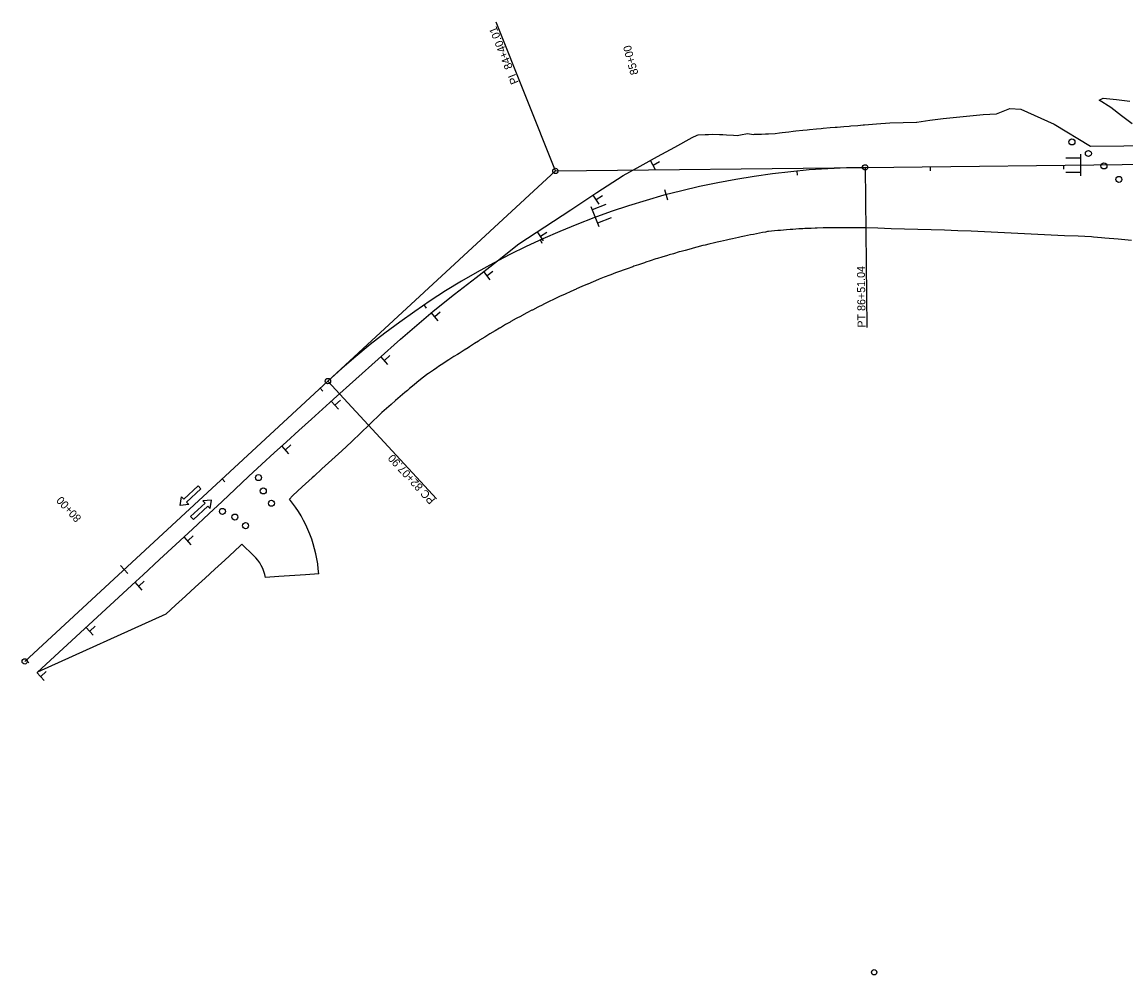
# Model space of a CAD drawing. Extents: x 1710760 to 1712674, y 548603 to 551129.
# Drawn here: x 1710760 to 1711587, y 548603 to 549317 of the extents above; entities that cross this region are included whole.
import ezdxf

# ---------------------------------------------------------------- set-up
doc = ezdxf.new("R2010")
doc.units = 0
for name, color, linetype in [('R_Horz Alg', 7, 'Continuous'), ('R_Horz Alg Annot', 7, 'Continuous'), ('R_MOT', 7, 'Continuous')]:
    doc.layers.add(name, color=color, linetype=linetype)

msp = doc.modelspace()

# ---------------------------------------------------------------- linework, layer by layer
at = {"layer": 'R_Horz Alg'}
for p, q in [((1711391.77, 549208.53), (1711733, 549212.35)), ((1711391.77, 549208.53), (1711733, 549212.35)), ((1710761.95, 548838.38), (1710989.21, 549048.39)), ((1710761.95, 548838.38), (1710989.21, 549048.39))]:
    msp.add_line(p, q, dxfattribs=at)
msp.add_arc((1711398.54, 548605.45), 603.11, 90.64281, 132.74131, dxfattribs=at)
msp.add_arc((1711398.54, 548605.45), 603.11, 90.64281, 132.74131, dxfattribs=at)
at = {"layer": 'R_Horz Alg Annot'}
for p, q in [((1710989.21, 549048.39), (1711159.68, 549205.92)), ((1710989.21, 549048.39), (1711159.68, 549205.92)), ((1711159.68, 549205.92), (1711391.77, 549208.53)), ((1711159.68, 549205.92), (1711391.77, 549208.53))]:
    msp.add_line(p, q, dxfattribs=at)
for points in [[(1711159.68, 549205.92), (1711115.32, 549317.42)], [(1711440.76, 549206.08), (1711440.73, 549209.07)], [(1711540.75, 549207.2), (1711540.72, 549210.2)], [(1711341.11, 549202.81), (1711340.82, 549205.8)], [(1711391.77, 549208.53), (1711393.12, 549088.53)], [(1711241.49, 549191.9), (1711243.56, 549184.17)], [(1711149.75, 549151.57), (1711148.51, 549154.3)], [(1711063.03, 549103.01), (1711061.35, 549105.5)], [(1710989.21, 549048.39), (1711070.66, 548960.26)], [(1710985.45, 549040.83), (1710983.41, 549043.03)], [(1710912, 548972.96), (1710909.97, 548975.16)], [(1710833.81, 548910.23), (1710839.24, 548904.35)], [(1710765.12, 548837.22), (1710763.08, 548839.42)]]:
    msp.add_lwpolyline(points, dxfattribs=at)
for centre in [(1711391.77, 549208.53), (1711391.77, 549208.53), (1711159.68, 549205.92), (1711159.68, 549205.92), (1710989.21, 549048.39), (1710989.21, 549048.39), (1710761.95, 548838.38), (1710761.95, 548838.38), (1711398.54, 548605.45), (1711398.54, 548605.45)]:
    msp.add_circle(centre, 2, dxfattribs=at)
at = {"layer": 'R_MOT'}
for p, q in [((1711490.29, 549248.71), (1711500.24, 549252.66)), ((1711553.08, 549218.34), (1711553.08, 549202.34)), ((1711234.71, 549206.71), (1711230.88, 549213.73)), ((1711232.91, 549210.26), (1711237.7, 549212.87)), ((1711542.16, 549215.7), (1711553.08, 549215.7)), ((1711542.16, 549204.84), (1711553.08, 549204.84)), ((1711192.4, 549181.1), (1711188.02, 549187.79)), ((1711190.32, 549184.49), (1711194.89, 549187.48)), ((1711186.23, 549179.17), (1711192.14, 549164.31)), ((1711197.35, 549180.76), (1711187.2, 549176.72)), ((1711201.36, 549170.67), (1711191.21, 549166.63)), ((1711150.63, 549153.61), (1711146.26, 549160.31)), ((1711148.55, 549157.01), (1711153.12, 549160)), ((1711110.84, 549124.25), (1711105.93, 549130.57)), ((1711108.49, 549127.47), (1711112.8, 549130.81)), ((1711071.7, 549093.63), (1711066.5, 549099.71)), ((1711069.2, 549096.73), (1711073.35, 549100.28)), ((1711034.18, 549060.79), (1711028.85, 549066.76)), ((1711031.61, 549063.84), (1711035.68, 549067.48)), ((1710997.01, 549027.36), (1710991.68, 549033.32)), ((1710994.44, 549030.4), (1710998.51, 549034.04)), ((1710959.9, 548993.87), (1710954.55, 548999.82)), ((1710957.33, 548996.91), (1710961.39, 549000.56)), ((1710886.74, 548925.82), (1710881.32, 548931.71)), ((1710884.13, 548928.83), (1710888.15, 548932.53)), ((1710933.39, 548917.62), (1710924.76, 548926.17)), ((1710972.33, 548903.23), (1710952.37, 548901.91)), ((1710982.3, 548903.89), (1710972.33, 548903.23)), ((1710850.04, 548891.85), (1710844.63, 548897.75)), ((1710847.43, 548894.87), (1710851.46, 548898.56)), ((1710952.37, 548901.91), (1710942.35, 548901.24)), ((1710813.27, 548857.97), (1710807.87, 548863.87)), ((1710810.67, 548860.98), (1710814.7, 548864.67)), ((1710776.51, 548824.09), (1710771.1, 548829.99)), ((1710773.91, 548827.1), (1710777.93, 548830.79))]:
    msp.add_line(p, q, dxfattribs=at)
for points in [[(1711591.96, 549241.26), (1711583.97, 549247.29), (1711575.98, 549253.32), (1711567.17, 549258.94), (1711567.8, 549259.07), (1711570.16, 549260.38), (1711580.17, 549259.31), (1711590.19, 549258.2)], [(1711500.24, 549252.66), (1711508.52, 549252.06), (1711533.48, 549240.83), (1711560.71, 549224.42), (1711610.62, 549224.98)], [(1711308.24, 549233.31), (1711308.88, 549233.33), (1711314.08, 549233.52), (1711317.05, 549233.6), (1711319.27, 549233.64), (1711324.45, 549233.9), (1711327.53, 549234.32), (1711329.57, 549234.59), (1711334.7, 549235.24), (1711337.95, 549235.63), (1711339.83, 549235.85), (1711344.97, 549236.42), (1711348.39, 549236.77), (1711350.12, 549236.94), (1711355.27, 549237.43), (1711358.85, 549237.74), (1711360.42, 549237.88), (1711365.57, 549238.34), (1711369.32, 549238.68), (1711370.73, 549238.8), (1711375.9, 549239.2), (1711379.81, 549239.48), (1711381.07, 549239.57), (1711386.24, 549240.01), (1711390.32, 549240.41), (1711391.41, 549240.51), (1711400.36, 549241.23), (1711410.36, 549242.05), (1711420.36, 549242.08), (1711430.35, 549242.53), (1711430.43, 549242.54), (1711440.34, 549243.88), (1711450.32, 549245.11), (1711460.31, 549246.2), (1711470.3, 549247.21), (1711480.29, 549248.18), (1711490.29, 549248.71)], [(1711265.88, 549232.81), (1711266.66, 549232.92), (1711271.96, 549233.16), (1711274.32, 549233.28), (1711277.23, 549233.43), (1711282.58, 549233.19), (1711285.14, 549233.07), (1711287.92, 549232.92), (1711293.25, 549232.57), (1711295.97, 549232.37), (1711298.46, 549232.87), (1711303.55, 549233.92), (1711308.24, 549233.31)], [(1710845.2, 548898.2), (1710850.63, 548903.21), (1710862.95, 548914.62), (1710875.27, 548926.03), (1710887.59, 548937.44), (1710899.91, 548948.84), (1710909.81, 548958.17), (1710919.71, 548967.5), (1710929.61, 548976.83), (1710939.52, 548986.16), (1710948.84, 548994.59), (1710958.16, 549003.01), (1710967.48, 549011.44), (1710976.8, 549019.87), (1710993.47, 549034.87), (1711010.15, 549049.87), (1711026.82, 549064.87), (1711043.5, 549079.87), (1711055.73, 549090.4), (1711067.97, 549100.92), (1711084.06, 549113.47), (1711100.15, 549126.03), (1711116.24, 549138.58), (1711132.33, 549151.14), (1711151.83, 549163.97), (1711171.33, 549176.8), (1711190.83, 549189.63), (1711210.33, 549202.46), (1711223.3, 549209.57), (1711236.27, 549216.69), (1711249.24, 549223.8), (1711262.22, 549230.91), (1711265.88, 549232.81)], [(1711319.28, 549160.49), (1711318.73, 549160.39), (1711317.21, 549160.12), (1711314.77, 549159.67), (1711310.28, 549158.81), (1711308.08, 549158.37), (1711305.79, 549157.91), (1711301.31, 549156.98), (1711298.98, 549156.49), (1711296.83, 549156.05), (1711292.36, 549155.1), (1711289.89, 549154.56), (1711287.9, 549154.12), (1711283.44, 549153.11), (1711280.84, 549152.5), (1711278.99, 549152.05), (1711274.55, 549150.99), (1711271.83, 549150.32), (1711270.12, 549149.89), (1711265.69, 549148.76), (1711262.84, 549148.01), (1711261.28, 549147.59), (1711256.87, 549146.39), (1711253.9, 549145.55), (1711252.48, 549145.15), (1711248.09, 549143.88), (1711245, 549142.96), (1711243.72, 549142.57), (1711239.36, 549141.23), (1711236.14, 549140.25), (1711234.99, 549139.9), (1711230.64, 549138.53), (1711227.31, 549137.43), (1711226.31, 549137.1), (1711221.99, 549135.63), (1711218.54, 549134.43), (1711217.68, 549134.13), (1711213.37, 549132.64), (1711209.8, 549131.36), (1711209.07, 549131.1), (1711204.8, 549129.5), (1711201.13, 549128.09), (1711200.55, 549127.86), (1711196.3, 549126.19), (1711192.53, 549124.67), (1711192.07, 549124.48), (1711187.86, 549122.74), (1711183.97, 549121.13), (1711183.65, 549121), (1711179.44, 549119.23), (1711175.45, 549117.49), (1711175.27, 549117.4), (1711171.11, 549115.52), (1711167.03, 549113.64), (1711166.97, 549113.61), (1711162.83, 549111.71), (1711158.7, 549109.77), (1711158.63, 549109.74), (1711154.6, 549107.79), (1711150.51, 549105.76), (1711150.32, 549105.67), (1711146.44, 549103.72), (1711142.37, 549101.66), (1711142.05, 549101.49), (1711138.33, 549099.54), (1711134.32, 549097.38), (1711133.88, 549097.14), (1711130.32, 549095.19), (1711126.33, 549092.99), (1711125.77, 549092.68), (1711122.36, 549090.74), (1711118.42, 549088.44), (1711117.75, 549088.05), (1711114.5, 549086.12), (1711110.59, 549083.78), (1711109.8, 549083.31), (1711106.71, 549081.4), (1711102.85, 549078.97), (1711101.95, 549078.4), (1711099.01, 549076.52), (1711095.18, 549074.05), (1711094.17, 549073.39), (1711091.37, 549071.54), (1711087.48, 549069.16), (1711086.33, 549068.46), (1711083.59, 549066.77), (1711079.73, 549064.34), (1711078.47, 549063.54), (1711075.97, 549061.76), (1711072.16, 549059.23), (1711070.8, 549058.34), (1711068.36, 549056.71), (1711064.57, 549054.15), (1711063.42, 549053.36), (1711063.11, 549053.15), (1711060.91, 549051.42), (1711057.35, 549048.56), (1711055.86, 549047.36), (1711053.81, 549045.67), (1711050.3, 549042.75), (1711048.72, 549041.45), (1711046.76, 549039.87), (1711043.3, 549036.89), (1711041.65, 549035.45), (1711039.87, 549033.88), (1711036.46, 549030.85), (1711034.73, 549029.29), (1711033.08, 549027.79), (1711029.64, 549024.8), (1711027.81, 549023.13), (1711026.29, 549021.7), (1711022.99, 549018.56), (1711021.1, 549016.75), (1711019.71, 549015.39), (1711013.99, 549009.94), (1711006.8, 549002.99), (1710999.6, 548996.04), (1710992.16, 548989.36), (1710984.68, 548982.72), (1710978.87, 548977.19), (1710977.44, 548975.82), (1710969.98, 548969.16), (1710962.83, 548962.58), (1710962.63, 548962.38), (1710960.38, 548960.06)], [(1711591.36, 549153.76), (1711581.35, 549154.67), (1711571.34, 549155.55), (1711568.96, 549155.75), (1711563, 549156.27), (1711562.99, 549156.27), (1711561.33, 549156.39), (1711551.32, 549156.99), (1711541.31, 549157.31), (1711531.31, 549157.74), (1711521.3, 549158.21), (1711511.3, 549158.68), (1711501.29, 549159.16), (1711491.28, 549159.64), (1711481.28, 549160.19), (1711471.27, 549160.64), (1711461.27, 549161.03), (1711451.26, 549161.43), (1711441.26, 549161.64), (1711431.34, 549161.88), (1711431.26, 549161.88), (1711421.25, 549162.15), (1711411.25, 549162.56), (1711401.24, 549162.96), (1711392.28, 549163.19), (1711391.32, 549163.21), (1711387.73, 549163.27), (1711383.17, 549163.3), (1711382.06, 549163.32), (1711378.61, 549163.35), (1711374.05, 549163.36), (1711372.8, 549163.36), (1711369.48, 549163.34), (1711364.92, 549163.28), (1711363.53, 549163.25), (1711360.35, 549163.17), (1711355.78, 549163.03), (1711354.25, 549162.97), (1711351.22, 549162.85), (1711346.65, 549162.64), (1711344.98, 549162.55), (1711342.08, 549162.38), (1711337.52, 549162.08), (1711335.71, 549161.95), (1711332.96, 549161.74), (1711328.39, 549161.37), (1711326.44, 549161.2), (1711323.83, 549160.96), (1711319.28, 549160.49)], [(1710924.76, 548926.17), (1710923.61, 548925.1), (1710919.17, 548921), (1710911.79, 548914.25), (1710904.45, 548907.47), (1710897.07, 548900.72), (1710889.72, 548893.93), (1710882.6, 548887.49), (1710882.31, 548887.22), (1710874.97, 548880.42), (1710867.59, 548873.68), (1710867.59, 548873.68)], [(1710867.59, 548873.68), (1710771.52, 548830.3), (1710845.2, 548898.2)]]:
    msp.add_lwpolyline(points, dxfattribs=at)
for points in [[(1710884.87, 548955.85), (1710878.34, 548955.3), (1710879.47, 548961.75), (1710881.16, 548959.91), (1710892.01, 548969.85), (1710894.03, 548967.64), (1710883.18, 548957.7)], [(1710900.86, 548952.84), (1710901.99, 548959.29), (1710895.46, 548958.73), (1710897.14, 548956.89), (1710886.3, 548946.95), (1710888.32, 548944.74), (1710899.17, 548954.68)]]:
    msp.add_lwpolyline(points, close=True, dxfattribs=at)
for centre in [(1711546.81, 549227.57), (1711559.08, 549218.95), (1711570.8, 549209.59), (1711581.93, 549199.54), (1710937.14, 548976.05), (1710940.75, 548966.13), (1710910.11, 548950.76), (1710946.86, 548956.88), (1710919.43, 548946.55), (1710927.42, 548940.08)]:
    msp.add_circle(centre, 2.25, dxfattribs=at)
for centre, radius, start, end in [((1710882.52, 548897.3), 100, 3.77333, 38.87274), ((1710913.94, 548896.33), 28.84, 9.80666, 47.57012)]:
    msp.add_arc(centre, radius, start, end, dxfattribs=at)

# ---------------------------------------------------------------- texts
at = {"layer": 'R_Horz Alg Annot'}
for s, rotation, p in [('PI  84+40.01', 111.69206, (1711132.24, 549272.19)), ('85+00', 104.99186, (1711221.9, 549278.74)), ('PT 86+51.04', 90.64281, (1711392.12, 549088.52)), ('PC 82+07.90', 132.74131, (1711069.92, 548959.58)), ('80+00', 132.74131, (1710804.79, 548946.05))]:
    msp.add_text(s, height=6, rotation=rotation, dxfattribs=at).set_placement(p)

doc.saveas('drawing.dxf')
